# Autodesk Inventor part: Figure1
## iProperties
Created: 2002-04
Part Number: Figure1
Document SubType Name: Modeling
Control State: 0
Master: False
Checked Out: False
PropertySet Name: Design Tracking Control
Shininess: 77.0
Angle Display Precision: 2
Document Length Units: 11269
Document Angle Units: 11283
Document Time Units: 11279
Document Mass Units: 11290
Document Length Units Precision: 3
Document Angle Units Precision: 2
Compacted: True
PropertySet Name: _Private Model Information
Density: 0.0
Volumn: 0.0
Area: 0.0
PropertySet Name: Model Information
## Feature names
1. Sweep1
2. Shell1
